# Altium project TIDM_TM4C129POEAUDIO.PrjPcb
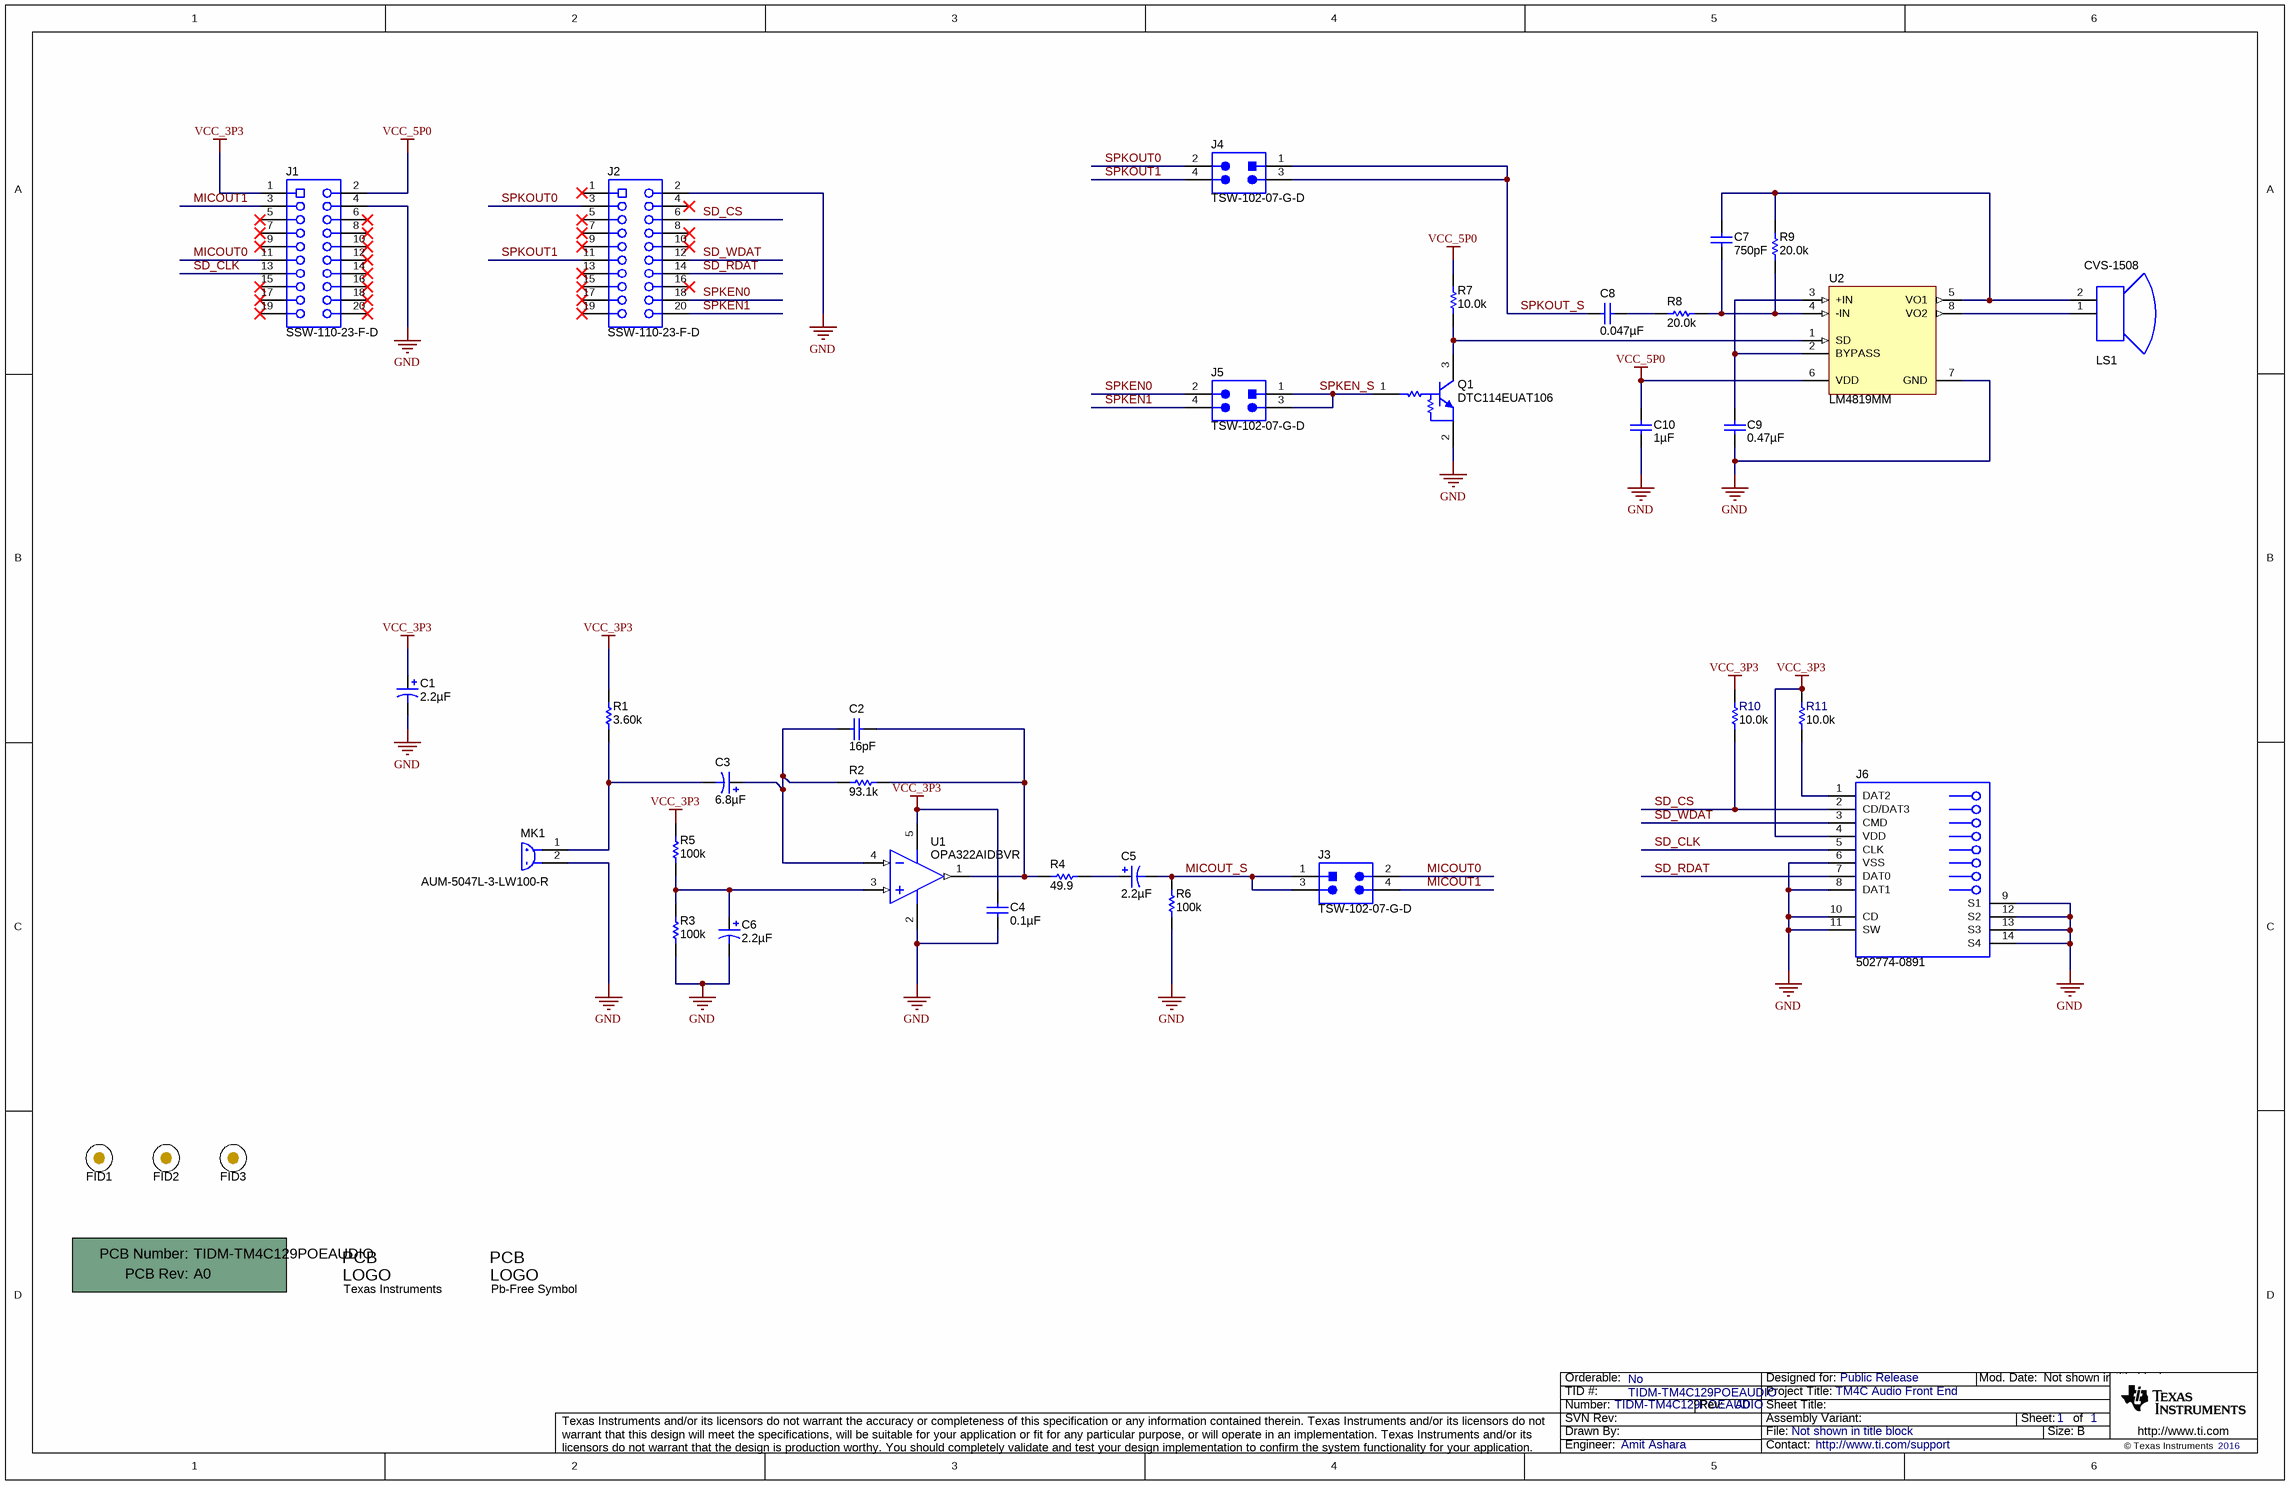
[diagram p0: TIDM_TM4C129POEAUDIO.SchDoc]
CopyrightYear: 2016; EVM_Orderable: No; PCB_Layout: Amit Ashara; PCB_Rev: A0; PRJ_Customer: Public Release; PRJ_Engineer: Amit Ashara; PRJ_Number: TIDM-TM4C129POEAUDIO; PRJ_Title: TM4C Audio Front End; SCH_Rev: A0; TechSupport: http://www.ti.com/support; TID: TIDM-TM4C129POEAUDIO
1 sheet, 38 parts. Net scope: global (net labels, ports and power ports of the same name join across sheets).
Board file: TIDM_TM4C129POEAUDIO.PcbDoc

## Sheet TIDM_TM4C129POEAUDIO.SchDoc
size 431 x 279 mm; Date: Not shown in title block; ApprovedBy: Not shown in title block; CheckedBy: Not shown in title block; Author: Not shown in title block; CompanyName: Not shown in title block; Engineer: Not shown in title block; Organization: Not shown in title block; Address1: Not shown in title block; Address2: Not shown in title block; Address3: Not shown in title block; Address4: Not shown in title block; DocumentNumber: 1; Revision: Use project parameter SCH_Rev; SheetNumber: 1; SheetTotal: 1; PageSetup: Record=PageOptions¦CenterHorizontal=True¦CenterVertical=True¦PrintScale=1.00¦XCorrection=1.00¦YCorrection=1.00¦PrintKind=0¦BorderSize=5000000¦LeftOffset=0¦BottomOffset=0¦Orientation=2¦PaperLength=1000¦PaperWidth=1000¦Scale=100¦PaperSource=15¦PrintQuality=600¦MediaType=1¦DitherType=10¦PaperKind=Letter¦PrintScaleMode=1

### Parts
!PCB  Printed Circuit Board  (value not drawn)  (mechanical)
C1  ValueDisplayed: 2.2µF  [3216-18]  (hidden comment: TPSA225K010R1800)
C2  ValueDisplayed: 16pF  [0603]  (hidden comment: GRM1885C1H160JA01D)
C3  ValueDisplayed: 6.8µF  [3216-18]  (hidden comment: T495A685K010ZTE1K8)
C4  ValueDisplayed: 0.1µF  [0603]  (hidden comment: 0603YC104JAT2A)
C5  ValueDisplayed: 2.2µF  [3216-18]  (hidden comment: TPSA225K010R1800)
C6  ValueDisplayed: 2.2µF  [3216-18]  (hidden comment: TPSA225K010R1800)
C7  ValueDisplayed: 750pF  [0402]  (hidden comment: GRM1555C1H751JA01D)
C8  ValueDisplayed: 0.047µF  [0603]  (hidden comment: GRM188R71C473KA01D)
C9  ValueDisplayed: 0.47µF  [0603]  (hidden comment: GRM188R71A474KA61D)
C10  ValueDisplayed: 1µF  [0603]  (hidden comment: GRM188R71E105KA12D)
FID1  Fiducial  [Fiducial10-20]  (value not drawn)
FID2  Fiducial  [Fiducial10-20]  (value not drawn)
FID3  Fiducial  [Fiducial10-20]  (value not drawn)
J1  SSW-110-23-F-D  [CONN_SSW-110-23-F-D]
J2  SSW-110-23-F-D  [CONN_SSW-110-23-F-D]
J3  TSW-102-07-G-D  [TSW-102-07-G-D]
J4  TSW-102-07-G-D  [TSW-102-07-G-D]
J5  TSW-102-07-G-D  [TSW-102-07-G-D]
J6  502774-0891  [Molex_502774-0891]
Logo1  Texas Instruments  [TI_Stacked_Overlay_Small]  (no BOM)
Logo2  Pb-Free Symbol  [Pb-Free_Overlay_Small]  (no BOM)
LS1  CVS-1508  [CUI_CVS-1508]
MK1  AUM-5047L-3-LW100-R  [PUI_AUM]
Q1  DTC114EUAT106  [SOT-323]
R1  ValueDisplayed: 3.60k  [0603]  (hidden comment: RC0603FR-073K6L)
R2  ValueDisplayed: 93.1k  [0603]  (hidden comment: CRCW060393K1FKEA)
R3  ValueDisplayed: 100k  [0603]  (hidden comment: RC0603FR-07100KL)
R4  ValueDisplayed: 49.9  [0603]  (hidden comment: RC0603FR-0749R9L)
R5  ValueDisplayed: 100k  [0603]  (hidden comment: RC0603FR-07100KL)
R6  ValueDisplayed: 100k  [0603]  (hidden comment: RC0603FR-07100KL)
R7  ValueDisplayed: 10.0k  [0603]  (hidden comment: RC0603FR-0710KL)
R8  ValueDisplayed: 20.0k  [0603]  (hidden comment: RC0603FR-0720KL)
R9  ValueDisplayed: 20.0k  [0603]  (hidden comment: RC0603FR-0720KL)
R10  ValueDisplayed: 10.0k  [0402]  (hidden comment: CRCW040210K0FKED)
R11  ValueDisplayed: 10.0k  [0402]  (hidden comment: CRCW040210K0FKED)
U1  OPA322AIDBVR  [DBV0005A_N]
U2  LM4819MM  [MUA08A_N]

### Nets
GND: C1.2(-) C4.2 C6.2(-) C9.2 C10.2 J1.4 J2.2 J6.6(VSS) J6.8(DAT1) J6.9(S1) J6.10(CD) J6.11(SW) J6.12(S2) J6.13(S3) J6.14(S4) MK1.2(-) Q1.2(E) R3.1 R6.1 U1.2(V-) U2.7(GND)
VCC_3P3: C1.1(+) C4.1 J1.1 J6.4(VDD) R1.2 R5.2 R10.1 R11.1 U1.5(V+)
VCC_5P0: C10.1 J1.2 R7.2 U2.6(VDD)
MICOUT0: J1.11 J3.2
MICOUT1: J1.3 J3.4
MICOUT_S: C5.2(-) J3.1 J3.3 R6.2
SD_CLK: J1.13 J6.5(CLK)
SD_CS: J2.6 J6.2(CD/DAT3) R10.2
SD_RDAT: J2.14 J6.7(DAT0)
SD_WDAT: J2.12 J6.3(CMD)
SPKEN0: J2.18 J5.2
SPKEN1: J2.20 J5.4
SPKEN_S: J5.1 J5.3 Q1.1(B)
SPKOUT0: J2.3 J4.2
SPKOUT1: J2.11 J4.4
SPKOUT_S: C8.2 J4.1 J4.3
NetC2_1: C2.1 R2.2 R4.1 U1.1(OUT)
NetC2_2: C2.2 C3.1(+) R2.1 U1.4(IN-)
NetC3_2: C3.2(-) MK1.1(+) R1.1
NetC5_1: C5.1(+) R4.2
NetC6_1: C6.1(+) R3.2 R5.1 U1.3(IN+)
NetC7_1: C7.1 LS1.2(-) R9.2 U2.5(VO1)
NetC7_2: C7.2 R8.2 R9.1 U2.4(-IN)
NetC8_1: C8.1 R8.1
NetC9_1: C9.1 U2.2(BYPASS) U2.3(+IN)
NetJ6_1: J6.1(DAT2) R11.2
NetLS1_1: LS1.1(+) U2.8(VO2)
NetQ1_3: Q1.3(C) R7.1 U2.1(SD)

Not connected (* = marked no-connect by the designer): J1 5* 6* 7* 8* 9* 10* 12* 14* 15* 16* 17* 18* 19* 20*; J2 1* 4* 5* 7* 8* 9* 10* 13* 15* 16* 17* 19*

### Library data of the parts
!PCB = PCB: Manufacturer: Any; PartNumber: TIDM-TM4C129POEAUDIO; SymbolCreator: a0412235
C1 C5 C6 = TPSA225K010R1800: CAP, TA, 2.2 µF, 10 V, +/- 10%, 1.8 ohm, SMD; Manufacturer: AVX; Polarized: Y; CompType: Capacitor; Value: 2.2uF; U/M: EA; Cap_F: 0.0000022; Tolerance_%: 10; Value1: 1.8 ohm; Value2: 10V; ESR_ohm: 1.8; IRMS_A: 0.184; TaMin_C: -55; TaMax_C: 125; Cap_Case: A; AEC Category: Q200
C2 = GRM1885C1H160JA01D: CAP, CERM, 16 pF, 50 V, +/- 5%, C0G/NP0, 0603; Manufacturer: MuRata; Polarized: N; CompType: Capacitor; Value: 16pF; U/M: EA; Cap_F: 0.000000000016; Tolerance_%: 5; Value1: Unknown; VDC_V: 50; Value2: 50V; TaMin_C: -55; TaMax_C: 125; AEC Category: Q200
C3 = T495A685K010ZTE1K8: CAP, TA, 6.8 µF, 10 V, +/- 10%, 1.8 ohm, SMD; Manufacturer: Kemet; Polarized: Y; CompType: Capacitor; Value: 6.8uF; U/M: EA; Cap_F: 0.0000068; Tolerance_%: 10; Value1: 1.8 ohm; Value2: 10V; ESR_ohm: 1.8; IRMS_A: 0.184; TaMin_C: -55; TaMax_C: 125; Cap_Case: A; AEC Category: Q200
C4 = 0603YC104JAT2A: CAP, CERM, 0.1 µF, 16 V, +/- 5%, X7R, 0603; Manufacturer: AVX; Polarized: N; CompType: Capacitor; Value: 0.1uF; U/M: EA; Cap_F: 0.0000001; Tolerance_%: 5; ESR_ohm: 0.039; Value1: 0.039 ohm; VDC_V: 16; Value2: 16V; TaMin_C: -55; TaMax_C: 125; AEC Category: Q200
C7 = GRM1555C1H751JA01D: CAP, CERM, 750 pF, 50 V, +/- 5%, C0G/NP0, 0402; Manufacturer: MuRata; Polarized: N; CompType: Capacitor; Value: 750pF; U/M: EA; Cap_F: 0.00000000075; Tolerance_%: 5; Value1: Unknown; VDC_V: 50; Value2: 50V; TaMin_C: -55; TaMax_C: 125; AEC Category: Q200
C8 = GRM188R71C473KA01D: CAP, CERM, 0.047 µF, 16 V, +/- 10%, X7R, 0603; Manufacturer: MuRata; Polarized: N; CompType: Capacitor; Value: 0.047uF; U/M: EA; Cap_F: 0.000000047; Tolerance_%: 10; Value1: Unknown; VDC_V: 16; Value2: 16V; TaMin_C: -55; TaMax_C: 125; AEC Category: Q200
C9 = GRM188R71A474KA61D: CAP, CERM, 0.47 µF, 10 V, +/- 10%, X7R, 0603; Manufacturer: MuRata; Polarized: N; CompType: Capacitor; Value: 0.47uF; U/M: EA; Cap_F: 0.00000047; Tolerance_%: 10; Value1: Unknown; Value2: 10V; TaMin_C: -55; TaMax_C: 125; AEC Category: Q200
C10 = GRM188R71E105KA12D: CAP, CERM, 1 µF, 25 V, +/- 10%, X7R, 0603; Manufacturer: MuRata; Polarized: N; CompType: Capacitor; Value: 1uF; U/M: EA; Cap_F: 0.000001; Tolerance_%: 10; Value1: Unknown; VDC_V: 25; Value2: 25V; TaMin_C: -55; TaMax_C: 125; AEC Category: Q200
FID1-FID3 = Fiducial: Fiducial mark.  There is nothing to buy or mount.; SymbolCreator: codlsc
J1 J2 = SSW-110-23-F-D: Connector, Receptacle, 100mil, 10x2, Gold plated, TH; Manufacturer: Samtec; SymbolCreator: a0412235
J3-J5 = TSW-102-07-G-D: Header, 100mil, 2x2, Gold, TH; Manufacturer: Samtec; SymbolCreator: a0412235; Pitch_mm: 2.54; Gender: Male; Shrouded: N; Row_Count: 2; Current_A: 6.3; Voltage_V: 550; Cert_CSA: Y
J6 = 502774-0891: Conncetor, micro SD Card, 1.1 mm, R/A, SMT; Manufacturer: Molex; SymbolCreator: Altium; CompType: Connector; U/M: EA
Logo1 = TI_Logo: Texas Instrument Corporate Signature; SymbolCreator: codlsc
Logo2 = Pb-Free: SymbolCreator: a0412235
LS1 = CVS-1508: Speaker, 8Ohms, 0.3W, 15mm Round, TH; Manufacturer: CUI Inc.; SymbolCreator: Altium
MK1 = AUM-5047L-3-LW100-R: Microphone, TH; Manufacturer: PUI Audio; SymbolCreator: Altium; Value: -47dB
Q1 = DTC114EUAT106, Rohm: Transistor, NPN, 50 V, 0.05 A, SOT-323; Manufacturer: Rohm; SymbolCreator: a0411947; PNP: 0; NPN: 1; Vceo_V: 50; Vcesat1_V: 0.3; Value: 50 V; IcRated_A: 0.05; Value1: 0.05 A; TaMin_C: -55; TaMax_C: 150; CompType: BJT; U/M: EA; AEC Category: Q101
R1 = RC0603FR-073K6L: RES, 3.60 k, 1%, 0.1 W, 0603; Manufacturer: Yageo America; CompType: Resistor; Value: 3.60k; Res_ohm: 3600; Value_Code: 3k60; Tolerance_%: 1; Power_W: 0.1; Value2: 0.1W; VDC_V: 150; TempCo: 200 ppm/C; U/M: EA; AEC Category: Q200
R2 = CRCW060393K1FKEA: RES, 93.1 k, 1%, 0.1 W, 0603; Manufacturer: Vishay-Dale; CompType: Resistor; Value: 93.1k; Res_ohm: 93100; Value_Code: 93k1; Tolerance_%: 1; Power_W: 0.1; Value2: 0.1W; VDC_V: 75; TempCo: 100 ppm/C; EIA_Code: E96; U/M: EA; AEC Category: Q200
R3 R5 R6 = RC0603FR-07100KL: RES, 100 k, 1%, 0.1 W, 0603; Manufacturer: Yageo America; CompType: Resistor; Value: 100k; Res_ohm: 100000; Tolerance_%: 1; Power_W: 0.1; Value2: 0.1W; VDC_V: 150; TempCo: 200 ppm/C; EIA_Code: E96; U/M: EA; AEC Category: Q200
R4 = RC0603FR-0749R9L: RES, 49.9, 1%, 0.1 W, 0603; Manufacturer: Yageo America; CompType: Resistor; Value: 49.9; Value_Code: 49R9; Tolerance_%: 1; Power_W: 0.1; Value2: 0.1W; VDC_V: 150; TempCo: 200 ppm/C; EIA_Code: E96; U/M: EA; AEC Category: Q200
R7 = RC0603FR-0710KL: RES, 10.0 k, 1%, 0.1 W, 0603; Manufacturer: Yageo America; CompType: Resistor; Value: 10.0k; Res_ohm: 10000; Value_Code: 10k0; Tolerance_%: 1; Power_W: 0.1; Value2: 0.1W; VDC_V: 150; TempCo: 200 ppm/C; EIA_Code: E96; U/M: EA; AEC Category: Q200
R8 R9 = RC0603FR-0720KL: RES, 20.0 k, 1%, 0.1 W, 0603; Manufacturer: Yageo America; CompType: Resistor; Value: 20.0k; Res_ohm: 20000; Value_Code: 20k0; Tolerance_%: 1; Power_W: 0.1; Value2: 0.1W; VDC_V: 150; TempCo: 200 ppm/C; EIA_Code: E96; U/M: EA; AEC Category: Q200
R10 R11 = CRCW040210K0FKED: RES, 10.0 k, 1%, 0.063 W, 0402; Manufacturer: Vishay-Dale; CompType: Resistor; Value: 10.0k; Res_ohm: 10000; Value_Code: 10k0; Tolerance_%: 1; Power_W: 0.063; Value2: 0.063W; VDC_V: 50; TempCo: 100 ppm/C; EIA_Code: E96; U/M: EA
U1 = OPA322AIDBVR: 20 MHz, Low Noise, RRIO, CMOS Operational Amplifier with Shutdown, 1.8 to 5.5 V, -40 to 125 degC, 5-pin SOT23 (DBV0005A), Green (RoHS & no Sb/Br); Manufacturer: Texas Instruments; Alternate PartNumber: Equivalent; CMRR(Min)(dB): 90; GBW(Typ)(MHz): 20; IIB(Max)(pA): 10; Iq per channel(Max)(mA): 1.9; Number of Channels: 1; Offset Drift(Typ)(uV/C): 1.8; Packing: LARGE T&R; Rating: Catalog; Sub Family: High Output Current Amplifier (>=50mA), Low Input Bias Current Amp (<=10pA), Low Noise Amp (<=10nV/rtHz), Low Supply Voltage Amplifier (<=2.7V), Precision Amplifier; Total Supply Voltage(Max)(+5V is 5, +/-5V is 10): 5.5; Vio (25C)(Max)(mV): 2
U2 = LM4819MM: 350mW Audio Power Amplifier with Shutdown Mode, 8-pin Mini SOIC; Manufacturer: Texas Instruments; PackageTopMarking: ZXTT*G19; PowerWise: N; CompType: Audio IC

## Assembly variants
001: not fitted FID1 FID2 FID3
